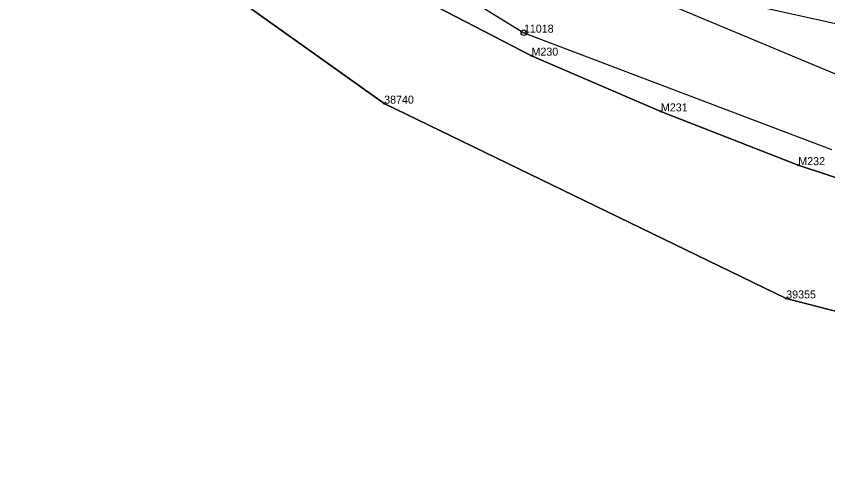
# Model space of a CAD drawing. Extents: x 7492083 to 7492670, y 5466693 to 5467065.
# Drawn here: x 7492278.6 to 7492392.7, y 5466748.5 to 5466813.8 of the extents above; entities that cross this region are included whole.
import ezdxf

# ---------------------------------------------------------------- set-up
doc = ezdxf.new("R2010")
doc.units = 0
for name, color, linetype in [('202-punkt graniczny', 7, 'Continuous'), ('202-punkt graniczny-Atr103', 7, 'Continuous'), ('203-punkt graniczny', 7, 'Continuous'), ('203-punkt graniczny-Atr103', 7, 'Continuous'), ('218-kontur użytku gruntowego', 7, 'Continuous'), ('219-działka ewidencyjna', 7, 'Continuous')]:
    doc.layers.add(name, color=color, linetype=linetype)

# ---------------------------------------------------------------- blocks, each defined once
blk = doc.blocks.new('203')
blk.add_circle((0, 0), 0.09)
blk = doc.blocks.new('202')
blk.add_circle((0, 0), 0.4)

msp = doc.modelspace()

# ---------------------------------------------------------------- linework, layer by layer
at = {"layer": '218-kontur użytku gruntowego'}
for points in [[(7492330.31, 5466801.52), (7492278.6, 5466838.41)], [(7492351.02, 5466808.26), (7492335.01, 5466816.56)], [(7492369.21, 5466800.43), (7492351.02, 5466808.26)], [(7492386.82, 5466774.16), (7492330.31, 5466801.52)], [(7492388.52, 5466792.88), (7492369.21, 5466800.43)], [(7492402, 5466788.41), (7492388.52, 5466792.88)], [(7492486.22, 5466748.54), (7492386.82, 5466774.16)]]:
    msp.add_lwpolyline(points, dxfattribs=at)
at = {"layer": '219-działka ewidencyjna'}
for points in [[(7492300.27, 5466842.12), (7492349.95, 5466811.49)], [(7492278.6, 5466838.41), (7492330.31, 5466801.52)], [(7492335.01, 5466816.56), (7492351.02, 5466808.26)], [(7492370.62, 5466815.37), (7492396.75, 5466804.43)], [(7492382.09, 5466815.36), (7492408.22, 5466809.61)], [(7492349.95, 5466811.49), (7492393.17, 5466795.09)], [(7492351.02, 5466808.26), (7492369.21, 5466800.43)], [(7492330.31, 5466801.52), (7492386.82, 5466774.16)], [(7492369.21, 5466800.43), (7492388.52, 5466792.88)], [(7492388.52, 5466792.88), (7492402, 5466788.41)], [(7492386.82, 5466774.16), (7492486.22, 5466748.54)]]:
    msp.add_lwpolyline(points, dxfattribs=at)

# ---------------------------------------------------------------- block references
at = {"layer": '202-punkt graniczny'}
msp.add_blockref('202', (7492349.95, 5466811.49), dxfattribs=at)
at = {"layer": '203-punkt graniczny'}
for p in [(7492351.02, 5466808.26), (7492330.31, 5466801.52), (7492369.21, 5466800.43), (7492388.52, 5466792.88), (7492386.82, 5466774.16)]:
    msp.add_blockref('203', p, dxfattribs=at)

# ---------------------------------------------------------------- texts
at = {"layer": '202-punkt graniczny-Atr103'}
msp.add_text('11018', height=1.125, dxfattribs=at).set_placement((7492349.95, 5466811.49))
at = {"layer": '203-punkt graniczny-Atr103'}
for s, p in [('M230', (7492351.02, 5466808.26)), ('38740', (7492330.31, 5466801.52)), ('M231', (7492369.21, 5466800.43)), ('M232', (7492388.52, 5466792.88)), ('39355', (7492386.82, 5466774.16))]:
    msp.add_text(s, height=1.125, dxfattribs=at).set_placement(p)

doc.saveas('drawing.dxf')
